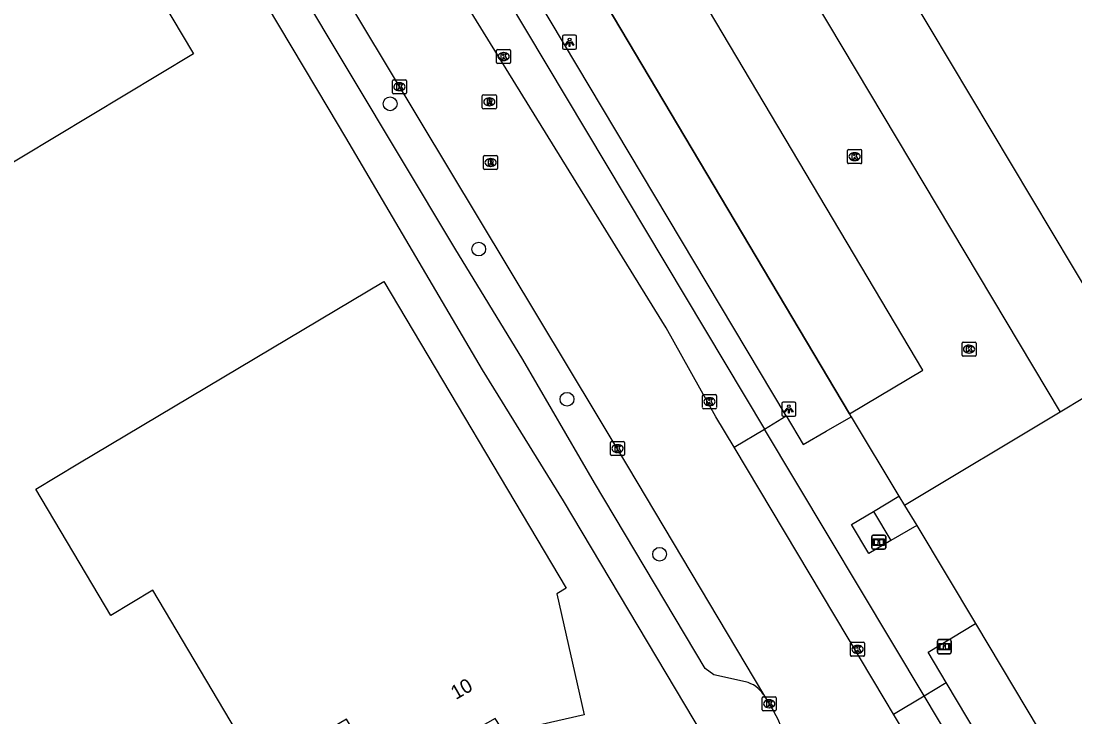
# Model space of a CAD drawing. Extents: x 156651 to 158072, y 387631 to 388990.
# Drawn here: x 157378 to 157452.9, y 388424.4 to 388473.9 of the extents above; entities that cross this region are included whole.
import ezdxf

# ---------------------------------------------------------------- set-up
doc = ezdxf.new("R2010")
doc.units = 0
for name, color, linetype in [('IMGEO_Boom', 7, 'Continuous'), ('IMGEO_Groenvoorziening', 7, 'Continuous'), ('IMGEO_Hek', 7, 'Continuous'), ('IMGEO_Informatiebord', 7, 'Continuous'), ('IMGEO_Kolk', 7, 'Continuous'), ('IMGEO_Lichtpunt', 7, 'Continuous'), ('IMGEO_Pand', 7, 'Continuous'), ('IMGEO_Pand_nummerreeks', 7, 'Continuous'), ('IMGEO_Parkeervlak_open', 7, 'Continuous'), ('IMGEO_Rijbaan_lokaal_gesloten', 7, 'Continuous'), ('IMGEO_Rioolput', 7, 'Continuous'), ('IMGEO_Voetpad_open', 7, 'Continuous')]:
    doc.layers.add(name, color=color, linetype=linetype)

msp = doc.modelspace()

# ---------------------------------------------------------------- linework, layer by layer
at = {"layer": 'IMGEO_Boom'}
for centre in [(157404.207, 388468.019), (157410.506, 388457.692), (157416.786, 388447.013), (157423.371, 388435.988)]:
    msp.add_circle(centre, 0.489, dxfattribs=at)
at = {"layer": 'IMGEO_Groenvoorziening'}
msp.add_lwpolyline([(157445.84, 388431.057), (157466.727, 388396.084)], dxfattribs=at)
at = {"layer": 'IMGEO_Hek'}
msp.add_lwpolyline([(157437.003, 388445.772), (157436.88, 388445.978), (157400.773, 388506.727), (157400.598, 388507.022)], dxfattribs=at)
at = {"layer": 'IMGEO_Informatiebord'}
for p, q in [((157438.465, 388436.454), (157438.465, 388437.254)), ((157438.465, 388437.254), (157438.465, 388436.454)), ((157438.565, 388437.354), (157439.355, 388437.354)), ((157439.355, 388437.354), (157438.565, 388437.354)), ((157439.455, 388437.254), (157439.455, 388436.454)), ((157439.455, 388436.454), (157439.455, 388437.254)), ((157439.355, 388436.354), (157438.565, 388436.354)), ((157438.565, 388436.354), (157439.355, 388436.354)), ((157443.125, 388429.021), (157443.125, 388429.821)), ((157443.125, 388429.821), (157443.125, 388429.021)), ((157443.225, 388429.921), (157444.015, 388429.921)), ((157444.015, 388429.921), (157443.225, 388429.921)), ((157444.115, 388429.821), (157444.115, 388429.021)), ((157444.115, 388429.021), (157444.115, 388429.821)), ((157444.015, 388428.921), (157443.225, 388428.921)), ((157443.225, 388428.921), (157444.015, 388428.921))]:
    msp.add_line(p, q, dxfattribs=at)
for points in [[(157438.566, 388437.086), (157439.354, 388437.086), (157439.354, 388436.622), (157438.566, 388436.622), (157438.566, 388437.086)], [(157438.631, 388437.021), (157438.631, 388436.687), (157438.906, 388436.687), (157438.907, 388436.9), (157439.011, 388436.901), (157439.012, 388436.687), (157439.289, 388436.687), (157439.289, 388437.021), (157439.013, 388437.021), (157439.013, 388436.941), (157438.907, 388436.941), (157438.907, 388437.021), (157438.631, 388437.021)], [(157443.226, 388429.653), (157444.014, 388429.653), (157444.014, 388429.189), (157443.226, 388429.189), (157443.226, 388429.653)], [(157443.291, 388429.588), (157443.291, 388429.254), (157443.566, 388429.254), (157443.567, 388429.467), (157443.671, 388429.468), (157443.672, 388429.254), (157443.949, 388429.254), (157443.949, 388429.588), (157443.673, 388429.588), (157443.673, 388429.508), (157443.567, 388429.508), (157443.567, 388429.588), (157443.291, 388429.588)]]:
    msp.add_lwpolyline(points, dxfattribs=at)
for centre, start, end in [((157438.565, 388437.254), 90, 180), ((157438.565, 388437.254), 90, 180), ((157439.355, 388437.254), 0, 90), ((157439.355, 388437.254), 360, 90), ((157438.565, 388436.454), 180, 270), ((157438.565, 388436.454), 180, 270), ((157439.355, 388436.454), 270, 0), ((157439.355, 388436.454), 270, 0), ((157443.225, 388429.821), 90, 180), ((157443.225, 388429.821), 90, 180), ((157444.015, 388429.821), 0, 90), ((157444.015, 388429.821), 360, 90), ((157443.225, 388429.021), 180, 270), ((157443.225, 388429.021), 180, 270), ((157444.015, 388429.021), 270, 0), ((157444.015, 388429.021), 270, 0)]:
    msp.add_arc(centre, 0.1, start, end, dxfattribs=at)
at = {"layer": 'IMGEO_Kolk'}
for p, q in [((157411.776, 388470.952), (157411.776, 388471.804)), ((157411.851, 388471.878), (157412.703, 388471.878)), ((157412.264, 388471.658), (157412.289, 388471.658)), ((157412.777, 388471.804), (157412.777, 388470.952)), ((157412.703, 388470.878), (157411.851, 388470.878)), ((157412.287, 388471.098), (157412.262, 388471.098)), ((157404.369, 388468.806), (157404.369, 388469.658)), ((157404.444, 388469.732), (157405.296, 388469.732)), ((157404.857, 388469.512), (157404.882, 388469.512)), ((157405.37, 388469.658), (157405.37, 388468.806)), ((157405.296, 388468.732), (157404.444, 388468.732)), ((157404.88, 388468.952), (157404.855, 388468.952)), ((157436.742, 388463.837), (157436.742, 388464.689)), ((157436.817, 388464.763), (157437.669, 388464.763)), ((157437.23, 388464.543), (157437.255, 388464.543)), ((157437.743, 388464.689), (157437.743, 388463.837)), ((157437.669, 388463.763), (157436.817, 388463.763)), ((157437.253, 388463.983), (157437.228, 388463.983)), ((157444.88, 388450.149), (157444.88, 388451.001)), ((157444.955, 388451.075), (157445.807, 388451.075)), ((157445.368, 388450.855), (157445.393, 388450.855)), ((157445.881, 388451.001), (157445.881, 388450.149)), ((157445.807, 388450.075), (157444.955, 388450.075)), ((157445.391, 388450.295), (157445.366, 388450.295)), ((157426.418, 388446.413), (157426.418, 388447.265)), ((157426.493, 388447.339), (157427.345, 388447.339)), ((157426.906, 388447.119), (157426.931, 388447.119)), ((157427.419, 388447.265), (157427.419, 388446.413)), ((157427.345, 388446.339), (157426.493, 388446.339)), ((157426.929, 388446.559), (157426.904, 388446.559)), ((157419.88, 388443.076), (157419.88, 388443.928)), ((157419.955, 388444.002), (157420.807, 388444.002)), ((157420.881, 388443.928), (157420.881, 388443.076)), ((157420.391, 388443.222), (157420.366, 388443.222)), ((157420.368, 388443.782), (157420.393, 388443.782)), ((157420.807, 388443.002), (157419.955, 388443.002)), ((157436.951, 388428.808), (157436.951, 388429.66)), ((157437.026, 388429.734), (157437.878, 388429.734)), ((157437.952, 388429.66), (157437.952, 388428.808)), ((157437.462, 388428.954), (157437.437, 388428.954)), ((157437.439, 388429.514), (157437.464, 388429.514)), ((157437.878, 388428.734), (157437.026, 388428.734)), ((157430.745, 388425.861), (157431.597, 388425.861)), ((157430.67, 388424.935), (157430.67, 388425.787)), ((157431.158, 388425.641), (157431.183, 388425.641)), ((157431.671, 388425.787), (157431.671, 388424.935)), ((157431.597, 388424.861), (157430.745, 388424.861)), ((157431.181, 388425.081), (157431.156, 388425.081))]:
    msp.add_line(p, q, dxfattribs=at)
for points in [[(157411.776, 388470.952), (157411.776, 388471.804)], [(157411.851, 388471.878), (157412.703, 388471.878)], [(157412.777, 388471.804), (157412.777, 388470.952)], [(157412.703, 388470.878), (157411.851, 388470.878)], [(157412.097, 388471.578), (157412.22, 388471.578), (157412.22, 388471.427), (157412.35, 388471.578), (157412.514, 388471.578), (157412.368, 388471.427), (157412.521, 388471.178), (157412.369, 388471.178), (157412.284, 388471.342), (157412.22, 388471.275), (157412.22, 388471.178), (157412.097, 388471.178), (157412.097, 388471.578)], [(157404.369, 388468.806), (157404.369, 388469.658)], [(157404.444, 388469.732), (157405.296, 388469.732)], [(157404.69, 388469.432), (157404.813, 388469.432), (157404.813, 388469.281), (157404.943, 388469.432), (157405.107, 388469.432), (157404.961, 388469.281), (157405.114, 388469.032), (157404.962, 388469.032), (157404.877, 388469.196), (157404.813, 388469.129), (157404.813, 388469.032), (157404.69, 388469.032), (157404.69, 388469.432)], [(157405.37, 388469.658), (157405.37, 388468.806)], [(157405.296, 388468.732), (157404.444, 388468.732)], [(157436.742, 388463.837), (157436.742, 388464.689)], [(157436.817, 388464.763), (157437.669, 388464.763)], [(157437.063, 388464.463), (157437.186, 388464.463), (157437.186, 388464.312), (157437.316, 388464.463), (157437.48, 388464.463), (157437.334, 388464.312), (157437.487, 388464.063), (157437.335, 388464.063), (157437.25, 388464.227), (157437.186, 388464.16), (157437.186, 388464.063), (157437.063, 388464.063), (157437.063, 388464.463)], [(157437.743, 388464.689), (157437.743, 388463.837)], [(157437.669, 388463.763), (157436.817, 388463.763)], [(157444.88, 388450.149), (157444.88, 388451.001)], [(157444.955, 388451.075), (157445.807, 388451.075)], [(157445.201, 388450.775), (157445.324, 388450.775), (157445.324, 388450.624), (157445.454, 388450.775), (157445.618, 388450.775), (157445.472, 388450.624), (157445.625, 388450.375), (157445.473, 388450.375), (157445.388, 388450.539), (157445.324, 388450.472), (157445.324, 388450.375), (157445.201, 388450.375), (157445.201, 388450.775)], [(157445.881, 388451.001), (157445.881, 388450.149)], [(157445.807, 388450.075), (157444.955, 388450.075)], [(157426.418, 388446.413), (157426.418, 388447.265)], [(157426.493, 388447.339), (157427.345, 388447.339)], [(157426.739, 388447.039), (157426.862, 388447.039), (157426.862, 388446.888), (157426.992, 388447.039), (157427.156, 388447.039), (157427.01, 388446.888), (157427.163, 388446.639), (157427.011, 388446.639), (157426.926, 388446.803), (157426.862, 388446.736), (157426.862, 388446.639), (157426.739, 388446.639), (157426.739, 388447.039)], [(157427.419, 388447.265), (157427.419, 388446.413)], [(157427.345, 388446.339), (157426.493, 388446.339)], [(157419.88, 388443.076), (157419.88, 388443.928)], [(157419.955, 388444.002), (157420.807, 388444.002)], [(157420.881, 388443.928), (157420.881, 388443.076)], [(157420.201, 388443.702), (157420.324, 388443.702), (157420.324, 388443.551), (157420.454, 388443.702), (157420.618, 388443.702), (157420.472, 388443.551), (157420.625, 388443.302), (157420.473, 388443.302), (157420.388, 388443.466), (157420.324, 388443.399), (157420.324, 388443.302), (157420.201, 388443.302), (157420.201, 388443.702)], [(157420.807, 388443.002), (157419.955, 388443.002)], [(157436.951, 388428.808), (157436.951, 388429.66)], [(157437.026, 388429.734), (157437.878, 388429.734)], [(157437.952, 388429.66), (157437.952, 388428.808)], [(157437.272, 388429.434), (157437.395, 388429.434), (157437.395, 388429.283), (157437.525, 388429.434), (157437.689, 388429.434), (157437.543, 388429.283), (157437.696, 388429.034), (157437.544, 388429.034), (157437.459, 388429.198), (157437.395, 388429.131), (157437.395, 388429.034), (157437.272, 388429.034), (157437.272, 388429.434)], [(157437.878, 388428.734), (157437.026, 388428.734)], [(157430.745, 388425.861), (157431.597, 388425.861)], [(157430.67, 388424.935), (157430.67, 388425.787)], [(157430.991, 388425.561), (157431.114, 388425.561), (157431.114, 388425.41), (157431.244, 388425.561), (157431.408, 388425.561), (157431.262, 388425.41), (157431.415, 388425.161), (157431.263, 388425.161), (157431.178, 388425.325), (157431.114, 388425.258), (157431.114, 388425.161), (157430.991, 388425.161), (157430.991, 388425.561)], [(157431.671, 388425.787), (157431.671, 388424.935)], [(157431.597, 388424.861), (157430.745, 388424.861)]]:
    msp.add_lwpolyline(points, dxfattribs=at)
for centre, start, end in [((157411.853, 388471.802), 91.55205, 178.44795), ((157411.853, 388471.802), 91.55205, 178.44795), ((157412.701, 388471.802), 1.55205, 88.44795), ((157412.701, 388471.802), 1.55205, 88.44795), ((157411.853, 388470.954), 181.55205, 268.44795), ((157411.853, 388470.954), 181.55205, 268.44795), ((157412.701, 388470.954), 271.55205, 358.44795), ((157412.701, 388470.954), 271.55205, 358.44795), ((157404.446, 388469.656), 91.55205, 178.44795), ((157404.446, 388469.656), 91.55205, 178.44795), ((157405.294, 388469.656), 1.55205, 88.44795), ((157405.294, 388469.656), 1.55205, 88.44795), ((157404.446, 388468.808), 181.55205, 268.44795), ((157404.446, 388468.808), 181.55205, 268.44795), ((157405.294, 388468.808), 271.55205, 358.44795), ((157405.294, 388468.808), 271.55205, 358.44795), ((157436.819, 388464.687), 91.55205, 178.44795), ((157436.819, 388464.687), 91.55205, 178.44795), ((157437.667, 388464.687), 1.55205, 88.44795), ((157437.667, 388464.687), 1.55205, 88.44795), ((157436.819, 388463.839), 181.55205, 268.44795), ((157436.819, 388463.839), 181.55205, 268.44795), ((157437.667, 388463.839), 271.55205, 358.44795), ((157437.667, 388463.839), 271.55205, 358.44795), ((157444.957, 388450.999), 91.55205, 178.44795), ((157444.957, 388450.999), 91.55205, 178.44795), ((157445.805, 388450.999), 1.55205, 88.44795), ((157445.805, 388450.999), 1.55205, 88.44795), ((157444.957, 388450.151), 181.55205, 268.44795), ((157444.957, 388450.151), 181.55205, 268.44795), ((157445.805, 388450.151), 271.55205, 358.44795), ((157445.805, 388450.151), 271.55205, 358.44795), ((157426.495, 388447.263), 91.55205, 178.44795), ((157426.495, 388447.263), 91.55205, 178.44795), ((157427.343, 388447.263), 1.55205, 88.44795), ((157427.343, 388447.263), 1.55205, 88.44795), ((157426.495, 388446.415), 181.55205, 268.44795), ((157426.495, 388446.415), 181.55205, 268.44795), ((157427.343, 388446.415), 271.55205, 358.44795), ((157427.343, 388446.415), 271.55205, 358.44795), ((157419.957, 388443.926), 91.55205, 178.44795), ((157419.957, 388443.926), 91.55205, 178.44795), ((157420.805, 388443.926), 1.55205, 88.44795), ((157420.805, 388443.926), 1.55205, 88.44795), ((157419.957, 388443.078), 181.55205, 268.44795), ((157419.957, 388443.078), 181.55205, 268.44795), ((157420.805, 388443.078), 271.55205, 358.44795), ((157420.805, 388443.078), 271.55205, 358.44795), ((157437.028, 388429.658), 91.55205, 178.44795), ((157437.028, 388429.658), 91.55205, 178.44795), ((157437.876, 388429.658), 1.55205, 88.44795), ((157437.876, 388429.658), 1.55205, 88.44795), ((157437.028, 388428.81), 181.55205, 268.44795), ((157437.028, 388428.81), 181.55205, 268.44795), ((157437.876, 388428.81), 271.55205, 358.44795), ((157437.876, 388428.81), 271.55205, 358.44795), ((157430.747, 388425.785), 91.55205, 178.44795), ((157430.747, 388425.785), 91.55205, 178.44795), ((157431.595, 388425.785), 1.55205, 88.44795), ((157431.595, 388425.785), 1.55205, 88.44795), ((157430.747, 388424.937), 181.55205, 268.44795), ((157430.747, 388424.937), 181.55205, 268.44795), ((157431.595, 388424.937), 271.55205, 358.44795), ((157431.595, 388424.937), 271.55205, 358.44795)]:
    msp.add_arc(centre, 0.0765, start, end, dxfattribs=at)
for centre, major_axis, ratio, start_param, end_param in [((157412.263, 388471.378), (-0.387, 0.002), 0.722429, 4.712389, 7.853982), ((157412.288, 388471.378), (-0.39, 0.002), 0.717154, 1.570796, 4.712389), ((157404.856, 388469.232), (-0.387, 0.002), 0.722429, 4.712389, 7.853982), ((157404.881, 388469.232), (-0.39, 0.002), 0.717154, 1.570796, 4.712389), ((157437.229, 388464.263), (-0.387, 0.002), 0.722429, 4.712389, 7.853982), ((157437.254, 388464.263), (-0.39, 0.002), 0.717154, 1.570796, 4.712389), ((157445.367, 388450.575), (-0.387, 0.002), 0.722429, 4.712389, 7.853982), ((157445.392, 388450.575), (-0.39, 0.002), 0.717154, 1.570796, 4.712389), ((157426.905, 388446.839), (-0.387, 0.002), 0.722429, 4.712389, 7.853982), ((157426.93, 388446.839), (-0.39, 0.002), 0.717154, 1.570796, 4.712389), ((157420.367, 388443.502), (-0.387, 0.002), 0.722429, 4.712389, 7.853982), ((157420.392, 388443.502), (-0.39, 0.002), 0.717154, 1.570796, 4.712389), ((157437.438, 388429.234), (-0.387, 0.002), 0.722429, 4.712389, 7.853982), ((157437.463, 388429.234), (-0.39, 0.002), 0.717154, 1.570796, 4.712389), ((157431.157, 388425.361), (-0.387, 0.002), 0.722429, 4.712389, 7.853982), ((157431.182, 388425.361), (-0.39, 0.002), 0.717154, 1.570796, 4.712389)]:
    msp.add_ellipse(centre, major_axis=major_axis, ratio=ratio, start_param=start_param, end_param=end_param, dxfattribs=at)
at = {"layer": 'IMGEO_Lichtpunt'}
for p, q in [((157416.472, 388472.796), (157416.472, 388471.989)), ((157416.472, 388472.796), (157416.472, 388471.989)), ((157417.374, 388472.891), (157416.566, 388472.891)), ((157417.374, 388472.891), (157416.566, 388472.891)), ((157417.468, 388471.989), (157417.468, 388472.796)), ((157417.468, 388471.989), (157417.468, 388472.796)), ((157416.566, 388471.895), (157417.374, 388471.895)), ((157416.566, 388471.895), (157417.374, 388471.895)), ((157432.061, 388446.717), (157432.061, 388445.91)), ((157432.061, 388446.717), (157432.061, 388445.91)), ((157432.963, 388446.812), (157432.155, 388446.812)), ((157432.963, 388446.812), (157432.155, 388446.812)), ((157433.057, 388445.91), (157433.057, 388446.717)), ((157433.057, 388445.91), (157433.057, 388446.717)), ((157432.155, 388445.816), (157432.963, 388445.816)), ((157432.155, 388445.816), (157432.963, 388445.816))]:
    msp.add_line(p, q, dxfattribs=at)
for points in [[(157416.846, 388472.46), (157416.885, 388472.432), (157416.697, 388472.17), (157416.659, 388472.197), (157416.846, 388472.46)], [(157416.948, 388472.412), (157416.995, 388472.412), (157416.995, 388472.09), (157416.948, 388472.09), (157416.948, 388472.412)], [(157417.058, 388472.432), (157417.096, 388472.459), (157417.283, 388472.197), (157417.244, 388472.169), (157417.058, 388472.432)], [(157432.435, 388446.381), (157432.474, 388446.353), (157432.286, 388446.091), (157432.248, 388446.118), (157432.435, 388446.381)], [(157432.537, 388446.333), (157432.584, 388446.333), (157432.584, 388446.011), (157432.537, 388446.011), (157432.537, 388446.333)], [(157432.647, 388446.353), (157432.685, 388446.38), (157432.872, 388446.118), (157432.833, 388446.09), (157432.647, 388446.353)]]:
    msp.add_lwpolyline(points, dxfattribs=at)
for centre in [(157416.971, 388472.594), (157432.56, 388446.515)]:
    msp.add_circle(centre, 0.0994, dxfattribs=at)
for centre, start, end in [((157416.566, 388472.796), 90, 180), ((157416.566, 388472.796), 90, 180), ((157417.374, 388472.796), 0, 90), ((157417.374, 388472.796), 0, 90), ((157416.566, 388471.989), 180, 270), ((157416.566, 388471.989), 180, 270), ((157417.374, 388471.989), 270, 0), ((157417.374, 388471.989), 270, 360), ((157432.155, 388446.717), 90, 180), ((157432.155, 388446.717), 90, 180), ((157432.963, 388446.717), 0, 90), ((157432.963, 388446.717), 0, 90), ((157432.155, 388445.91), 180, 270), ((157432.155, 388445.91), 180, 270), ((157432.963, 388445.91), 270, 0), ((157432.963, 388445.91), 270, 360)]:
    msp.add_arc(centre, 0.0946, start, end, dxfattribs=at)
at = {"layer": 'IMGEO_Pand'}
for points in [[(157350.343, 388489.824), (157364.535, 388498.328), (157373.287, 388499.936), (157375.519, 388496.197), (157390.214, 388471.577), (157375.553, 388462.755), (157375.613, 388462.646), (157375.233, 388462.433), (157372.541, 388467.029), (157366.222, 388463.23), (157356.587, 388479.349), (157352.689, 388478.468), (157352.584, 388478.678), (157352.444, 388478.629), (157351.142, 388484.331), (157351.566, 388484.475), (157351.589, 388484.106), (157353.177, 388485.092), (157350.343, 388489.824)], [(157379.005, 388440.621), (157382.003, 388442.408), (157403.759, 388455.374), (157416.726, 388433.575), (157416.061, 388433.177), (157418.01, 388424.582), (157412.903, 388423.419), (157412.347, 388423.293), (157411.676, 388424.32), (157409.866, 388423.282), (157410.132, 388422.802), (157409.591, 388422.678), (157402.957, 388421.164), (157401.1, 388424.268), (157394.947, 388420.609), (157387.335, 388433.429), (157384.334, 388431.647), (157379.005, 388440.621)]]:
    msp.add_lwpolyline(points, dxfattribs=at)
at = {"layer": 'IMGEO_Parkeervlak_open'}
for points in [[(157415.297, 388519.009), (157410.154, 388515.931), (157451.864, 388446.103)], [(157415.297, 388519.009), (157426.672, 388500), (157457.056, 388449.224), (157451.864, 388446.103)], [(157436.88, 388445.978), (157442.103, 388449.082), (157426.4, 388475.502), (157410.729, 388501.867), (157405.996, 388509.831), (157400.773, 388506.727)], [(157400.773, 388506.727), (157436.88, 388445.978)], [(157451.864, 388446.103), (157440.797, 388439.451)], [(157436.88, 388445.978), (157437.003, 388445.772)]]:
    msp.add_lwpolyline(points, dxfattribs=at)
at = {"layer": 'IMGEO_Rijbaan_lokaal_gesloten'}
for points in [[(157383.032, 388505.544), (157421.092, 388442.257), (157430.755, 388426.017)], [(157428.669, 388443.598), (157427.382, 388445.752), (157423.836, 388452.097), (157406.064, 388480.897), (157396.411, 388497.052), (157395.535, 388498.696)], [(157440.013, 388424.616), (157439.413, 388425.619), (157428.669, 388443.598)], [(157430.755, 388426.017), (157431.523, 388424.771)], [(157449.717, 388408.375), (157440.013, 388424.616)]]:
    msp.add_lwpolyline(points, dxfattribs=at)
msp.add_arc((157425.727, 388421.425), 6.693, 311.78398, 29.99204, dxfattribs=at)
at = {"layer": 'IMGEO_Rioolput'}
for p, q in [((157410.761, 388467.732), (157410.761, 388468.584)), ((157410.836, 388468.658), (157411.688, 388468.658)), ((157411.762, 388468.584), (157411.762, 388467.732)), ((157411.272, 388467.878), (157411.247, 388467.878)), ((157411.249, 388468.438), (157411.274, 388468.438)), ((157411.688, 388467.658), (157410.836, 388467.658)), ((157410.851, 388463.42), (157410.851, 388464.272)), ((157410.926, 388464.346), (157411.778, 388464.346)), ((157411.339, 388464.126), (157411.364, 388464.126)), ((157411.852, 388464.272), (157411.852, 388463.42)), ((157411.778, 388463.346), (157410.926, 388463.346)), ((157411.362, 388463.566), (157411.337, 388463.566))]:
    msp.add_line(p, q, dxfattribs=at)
for points in [[(157410.761, 388467.732), (157410.761, 388468.584)], [(157410.836, 388468.658), (157411.688, 388468.658)], [(157411.762, 388468.584), (157411.762, 388467.732)], [(157411.35, 388468.356), (157411.098, 388468.358), (157411.098, 388467.958)], [(157411.098, 388467.958), (157411.222, 388467.958), (157411.222, 388468.12), (157411.233, 388468.12)], [(157411.276, 388468.277), (157411.222, 388468.277), (157411.222, 388468.196)], [(157411.222, 388468.196), (157411.274, 388468.196)], [(157411.28, 388468.091), (157411.351, 388467.958), (157411.491, 388467.958), (157411.426, 388468.084)], [(157411.688, 388467.658), (157410.836, 388467.658)], [(157410.851, 388463.42), (157410.851, 388464.272)], [(157410.926, 388464.346), (157411.778, 388464.346)], [(157411.852, 388464.272), (157411.852, 388463.42)], [(157411.778, 388463.346), (157410.926, 388463.346)], [(157411.44, 388464.044), (157411.188, 388464.046), (157411.188, 388463.646)], [(157411.188, 388463.646), (157411.312, 388463.646), (157411.312, 388463.808), (157411.323, 388463.808)], [(157411.366, 388463.965), (157411.312, 388463.965), (157411.312, 388463.884)], [(157411.312, 388463.884), (157411.364, 388463.884)], [(157411.37, 388463.779), (157411.441, 388463.646), (157411.581, 388463.646), (157411.516, 388463.772)]]:
    msp.add_lwpolyline(points, dxfattribs=at)
for centre, radius, start, end in [((157410.838, 388468.582), 0.0765, 91.55205, 178.44795), ((157410.838, 388468.582), 0.0765, 91.55205, 178.44795), ((157411.686, 388468.582), 0.0765, 1.55205, 88.44795), ((157411.686, 388468.582), 0.0765, 1.55205, 88.44795), ((157411.232, 388468.067), 0.0533, 26.02933, 88.69889), ((157411.258, 388468.385), 0.19, 274.7715, 282.96867), ((157411.282, 388468.181), 0.0964, 77.00612, 93.18647), ((157411.296, 388468.238), 0.0378, 276.66336, 79.67722), ((157411.349, 388468.246), 0.109, 350.36119, 89.41601), ((157411.347, 388468.246), 0.112, 277.58423, 350.98172), ((157411.331, 388468.031), 0.108, 29.51342, 73.79051), ((157410.838, 388467.734), 0.0765, 181.55205, 268.44795), ((157410.838, 388467.734), 0.0765, 181.55205, 268.44795), ((157411.686, 388467.734), 0.0765, 271.55205, 358.44795), ((157411.686, 388467.734), 0.0765, 271.55205, 358.44795), ((157410.928, 388464.27), 0.0765, 91.55205, 178.44795), ((157410.928, 388464.27), 0.0765, 91.55205, 178.44795), ((157411.776, 388464.27), 0.0765, 1.55205, 88.44795), ((157411.776, 388464.27), 0.0765, 1.55205, 88.44795), ((157410.928, 388463.422), 0.0765, 181.55205, 268.44795), ((157410.928, 388463.422), 0.0765, 181.55205, 268.44795), ((157411.322, 388463.755), 0.0533, 26.02933, 88.69889), ((157411.348, 388464.073), 0.19, 274.7715, 282.96867), ((157411.372, 388463.869), 0.0964, 77.00612, 93.18647), ((157411.386, 388463.926), 0.0378, 276.66336, 79.67722), ((157411.439, 388463.934), 0.109, 350.36119, 89.41601), ((157411.437, 388463.934), 0.112, 277.58423, 350.98172), ((157411.421, 388463.719), 0.108, 29.51342, 73.79051), ((157411.776, 388463.422), 0.0765, 271.55205, 358.44795), ((157411.776, 388463.422), 0.0765, 271.55205, 358.44795)]:
    msp.add_arc(centre, radius, start, end, dxfattribs=at)
for centre, major_axis, ratio, start_param, end_param in [((157411.248, 388468.158), (-0.387, 0.002), 0.722429, 4.712389, 7.853982), ((157411.273, 388468.158), (-0.39, 0.002), 0.717154, 1.570796, 4.712389), ((157411.338, 388463.846), (-0.387, 0.002), 0.722429, 4.712389, 7.853982), ((157411.363, 388463.846), (-0.39, 0.002), 0.717154, 1.570796, 4.712389)]:
    msp.add_ellipse(centre, major_axis=major_axis, ratio=ratio, start_param=start_param, end_param=end_param, dxfattribs=at)
at = {"layer": 'IMGEO_Voetpad_open'}
for points in [[(157376.205, 388506.903), (157389.391, 388485.151), (157399.772, 388467.72), (157401.022, 388465.621), (157410.746, 388449.094), (157416.517, 388439.8), (157427.8, 388420.86)], [(157432.385, 388445.838), (157399.747, 388500.478), (157403.127, 388502.525), (157400.55, 388506.883)], [(157429.48, 388426.914), (157427.224, 388427.414), (157426.614, 388427.868), (157418.749, 388441.074), (157413.653, 388449.828), (157408.813, 388457.752), (157382.545, 388501.61), (157382.297, 388502.147), (157382.296, 388502.573), (157383.032, 388505.544)], [(157399.804, 388496.799), (157430.832, 388444.891)], [(157430.832, 388444.891), (157432.385, 388445.838)], [(157432.385, 388445.838), (157433.586, 388443.796), (157435.209, 388444.735), (157437.003, 388445.772)], [(157437.003, 388445.772), (157440.394, 388440.112)], [(157428.669, 388443.598), (157430.832, 388444.891)], [(157442.194, 388425.919), (157430.832, 388444.891)], [(157438.587, 388439.035), (157440.394, 388440.112)], [(157440.394, 388440.112), (157440.797, 388439.451)], [(157440.797, 388439.451), (157441.658, 388438.039)], [(157439.827, 388436.966), (157438.257, 388436.051), (157437.015, 388438.114), (157438.587, 388439.035)], [(157438.587, 388439.035), (157439.827, 388436.966)], [(157441.658, 388438.039), (157439.827, 388436.966)], [(157441.658, 388438.039), (157445.84, 388431.057)], [(157443.743, 388426.865), (157442.469, 388429.038), (157445.84, 388431.057)], [(157442.194, 388425.919), (157443.743, 388426.865)], [(157466.727, 388396.084), (157463.326, 388394.073), (157453.443, 388410.621), (157443.743, 388426.865)], [(157440.013, 388424.616), (157442.194, 388425.919)], [(157480.832, 388361.226), (157451.89, 388409.685), (157442.194, 388425.919)]]:
    msp.add_lwpolyline(points, dxfattribs=at)
msp.add_arc((157429.04, 388424.934), 2.028, 32.26889, 77.47608, dxfattribs=at)

# ---------------------------------------------------------------- texts
at = {"layer": 'IMGEO_Pand_nummerreeks'}
msp.add_text('10', height=1, rotation=29.83344, dxfattribs=at).set_placement((157408.882, 388425.623))

doc.saveas('drawing.dxf')
